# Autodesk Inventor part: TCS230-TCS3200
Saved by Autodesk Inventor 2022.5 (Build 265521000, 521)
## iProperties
Created: 2024-12
Part Number: TCS230-TCS3200
Material: Generic
Document SubType Name: Modeling
Designer: AdminForWorker
Density: 1 g/cm^3
Appearance: Default
Title: TCS230-TCS3200 v1
Author: AdminForWorker
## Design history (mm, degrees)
feature "Body1"
body "Solid1"
